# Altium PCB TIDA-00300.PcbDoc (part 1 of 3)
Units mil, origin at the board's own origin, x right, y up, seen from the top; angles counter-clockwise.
Board outline 2685 x 3089 mil, 4 copper layers (Top Layer, L2_GND-PLANE, L3_PWR-PLANE, Bottom Layer), stack 63.6 mil thick; 196 components, 87 nets, 476 pads, 171 vias.
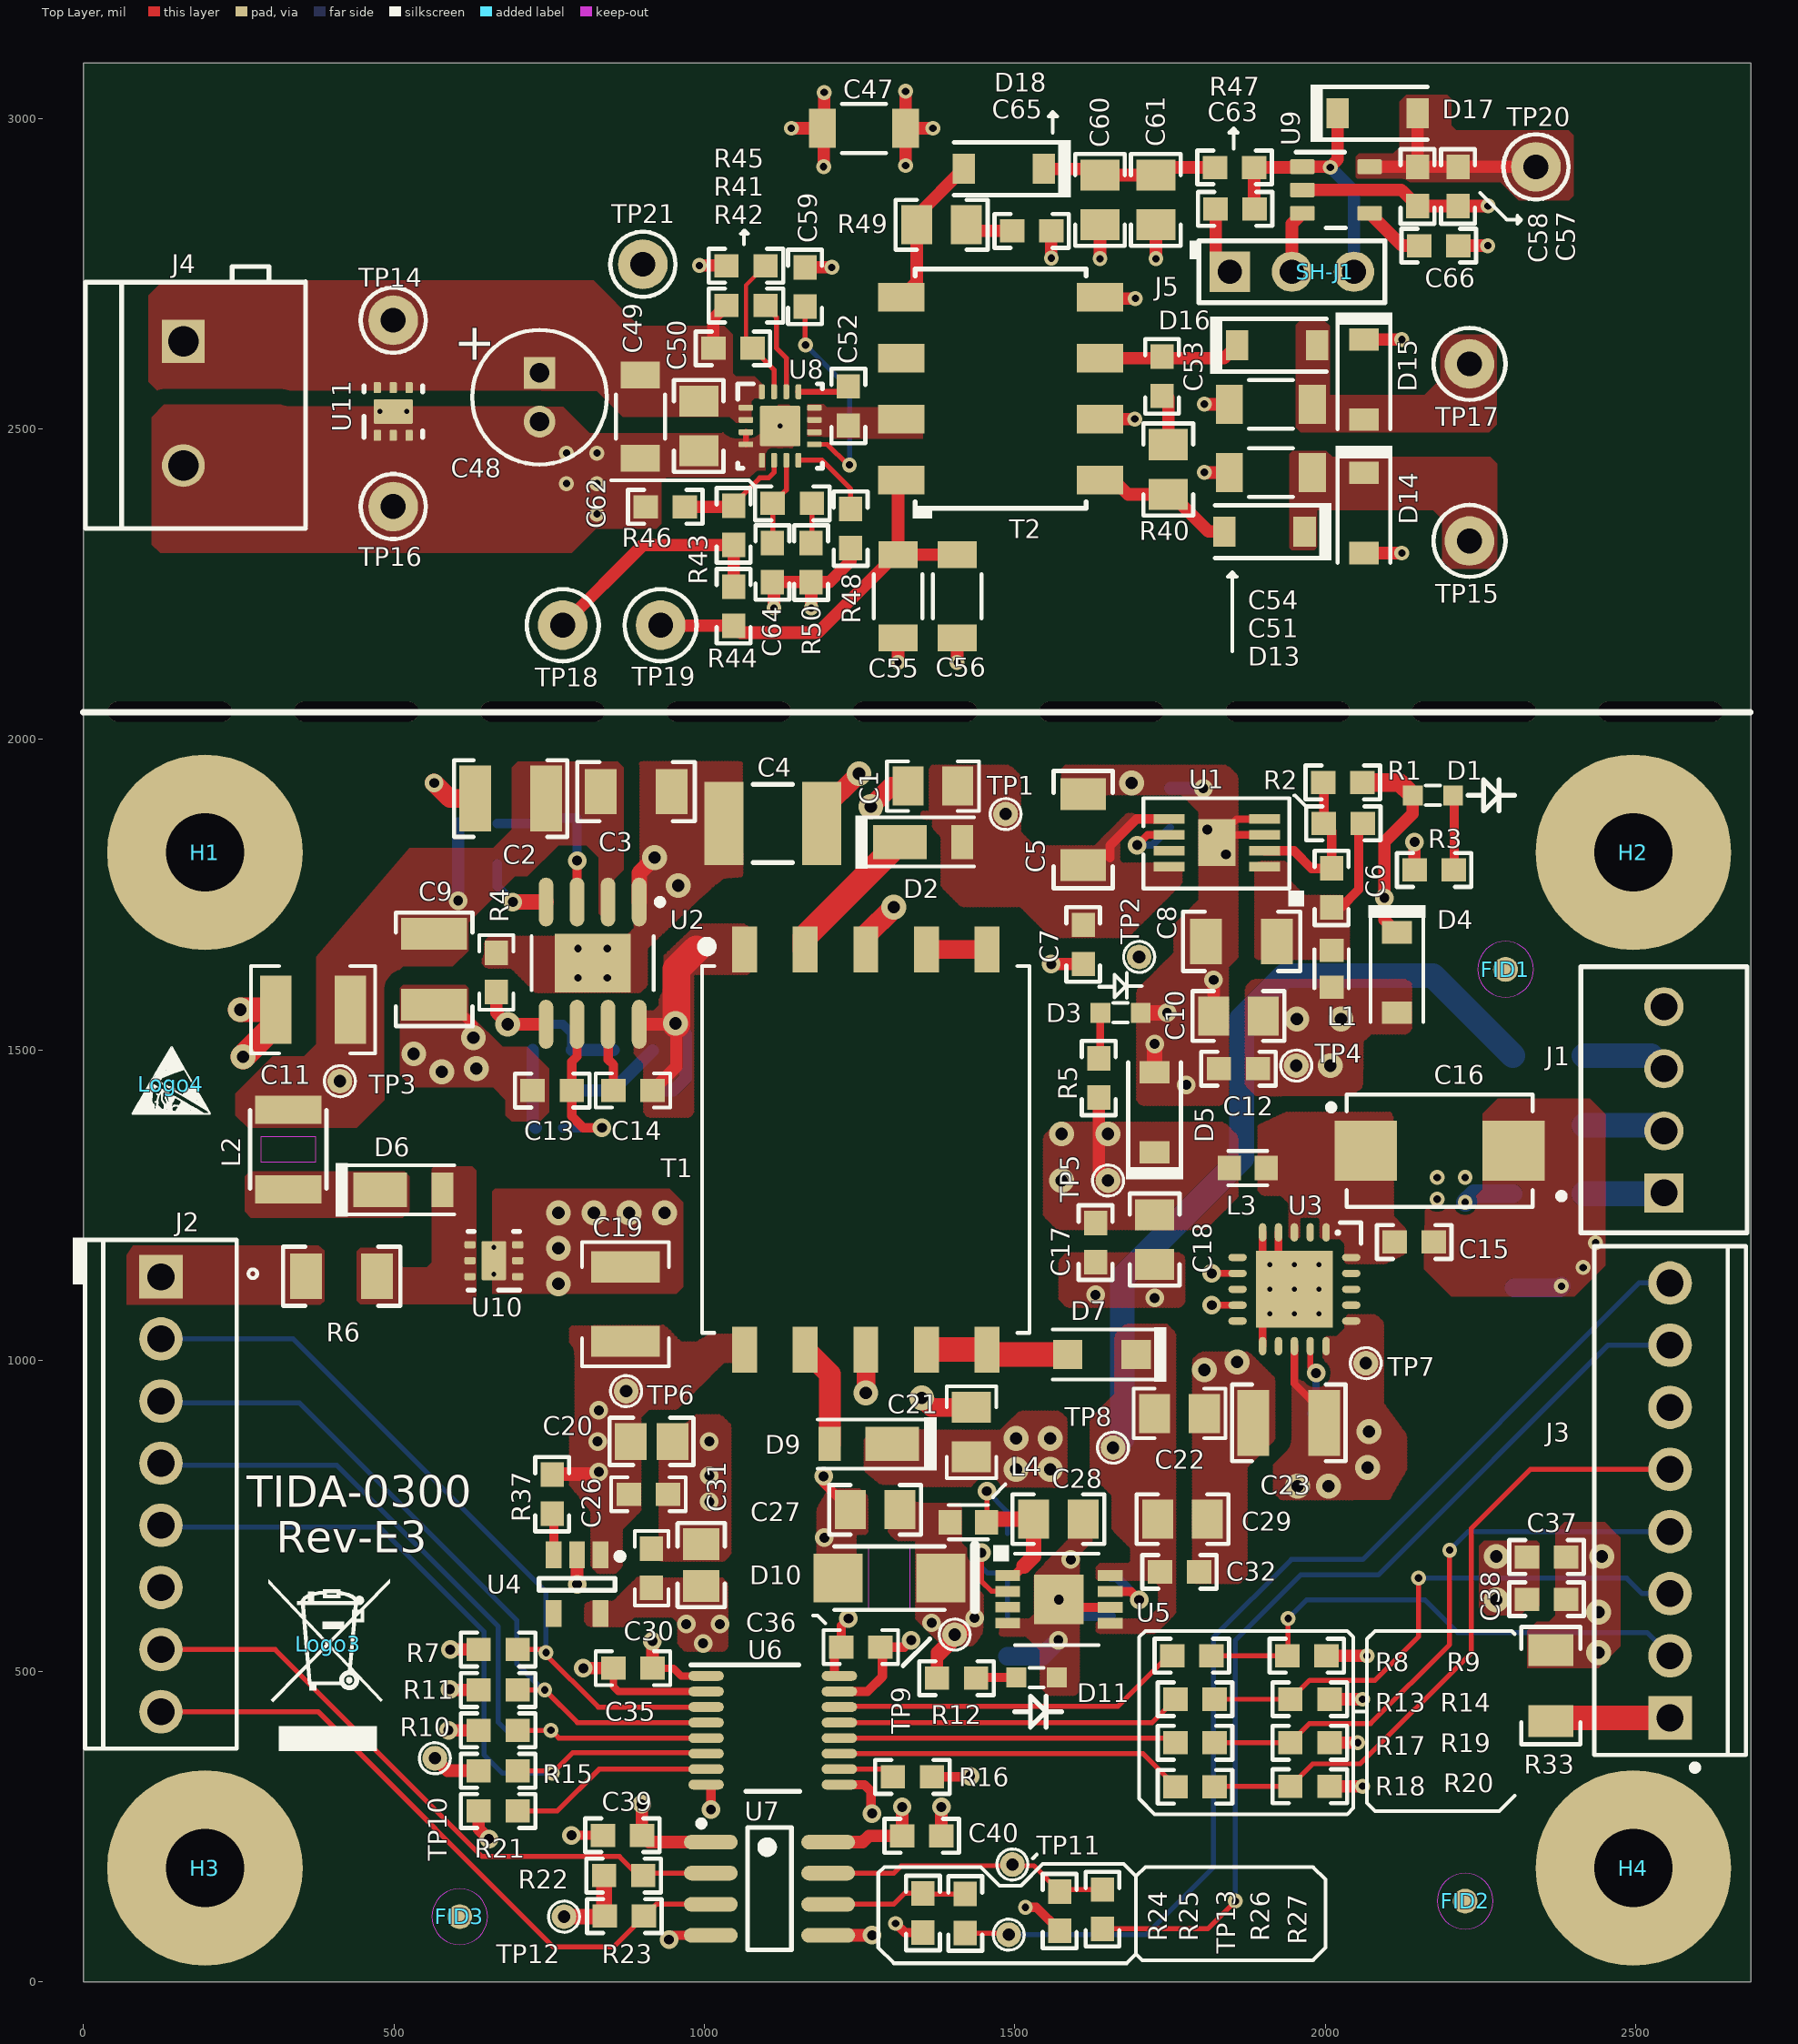
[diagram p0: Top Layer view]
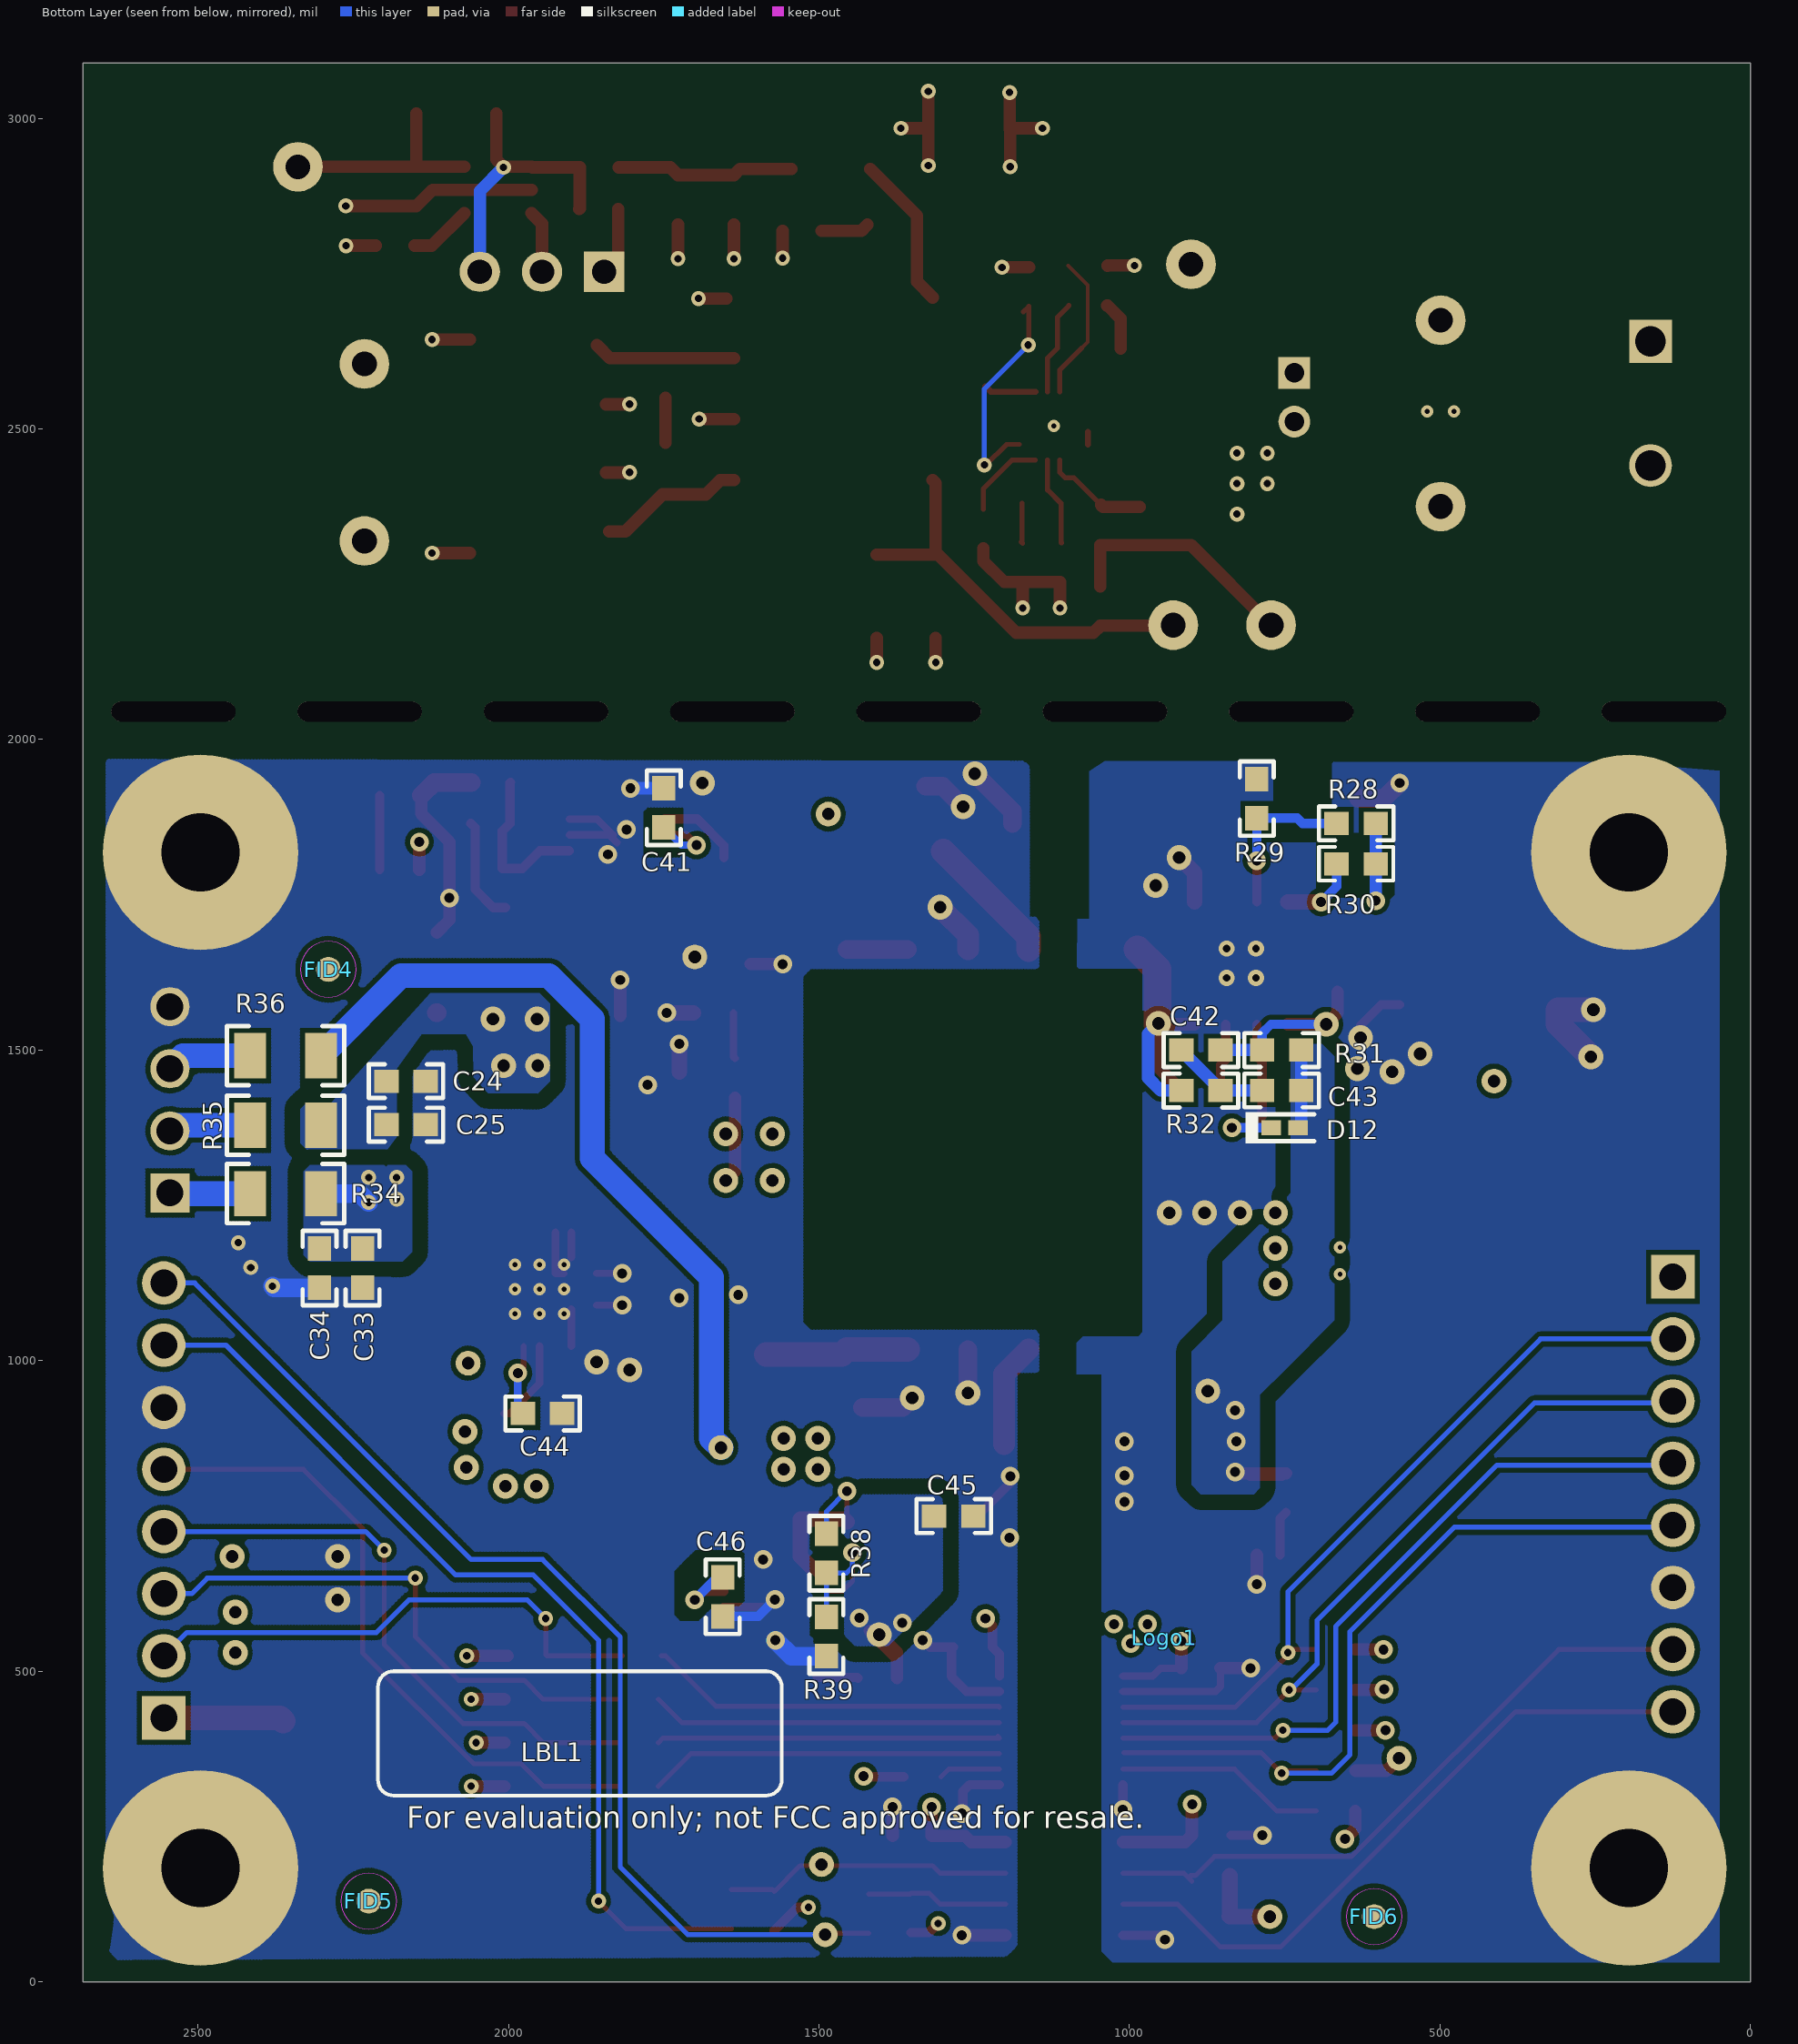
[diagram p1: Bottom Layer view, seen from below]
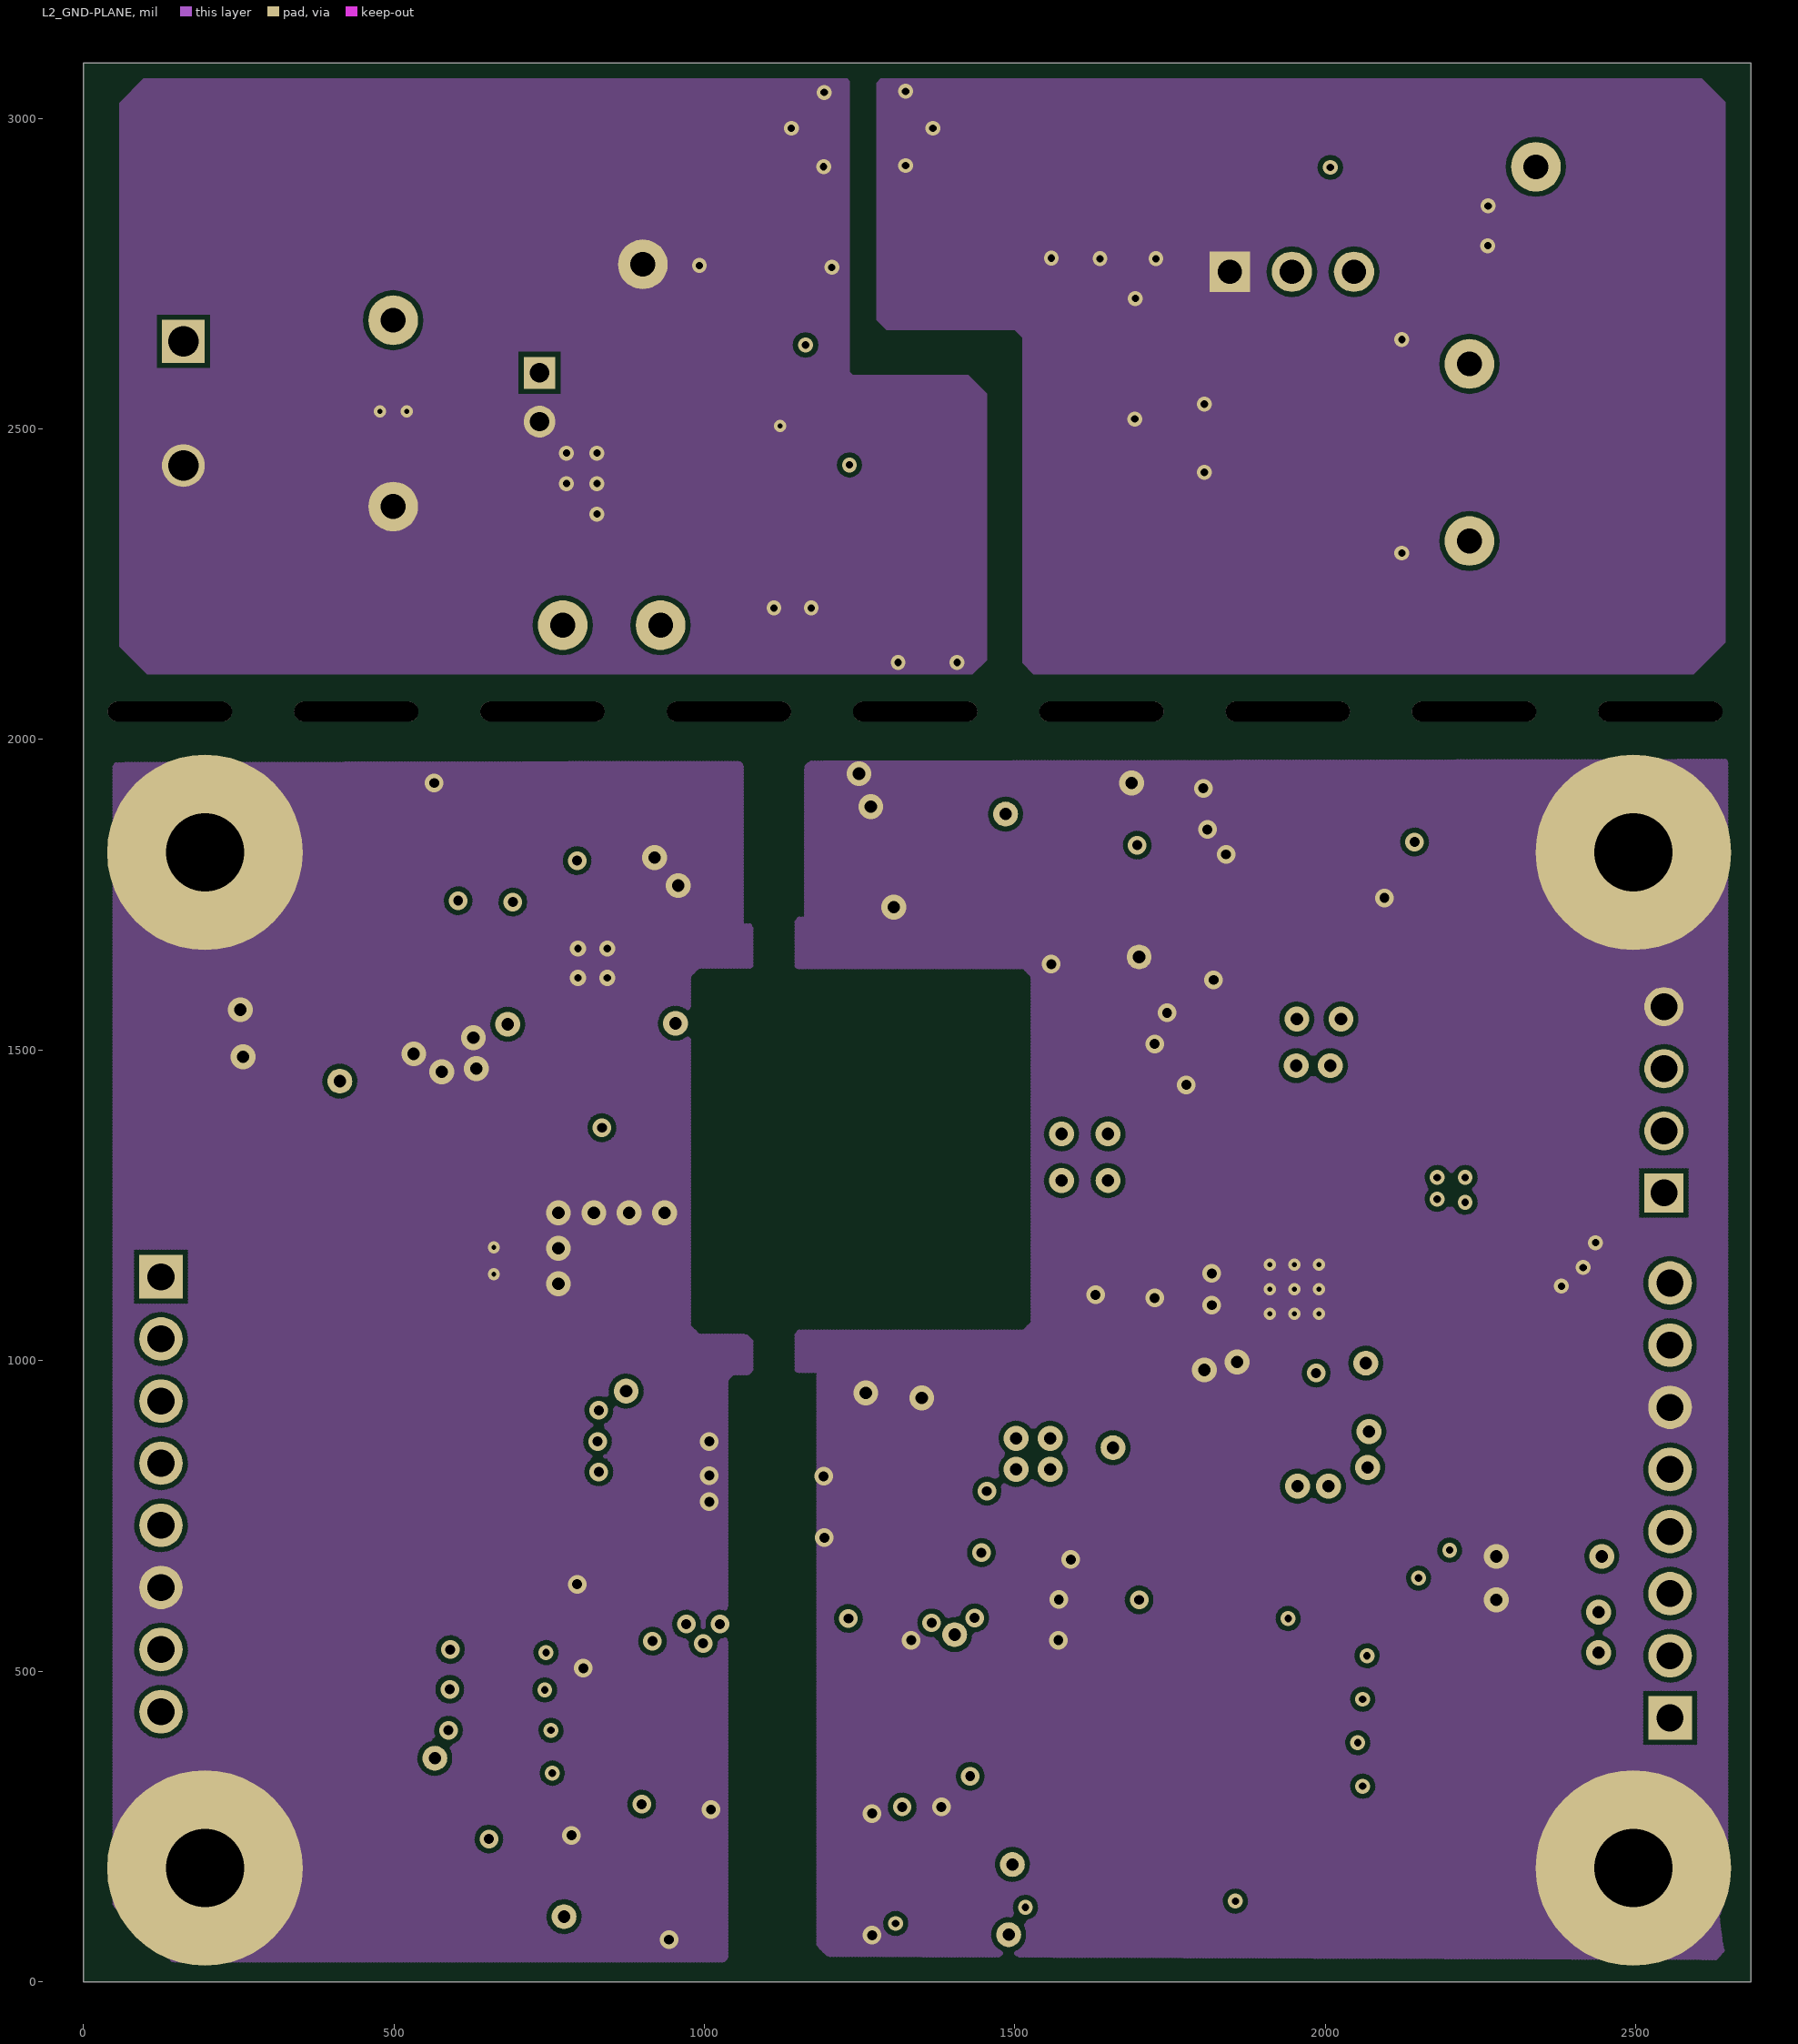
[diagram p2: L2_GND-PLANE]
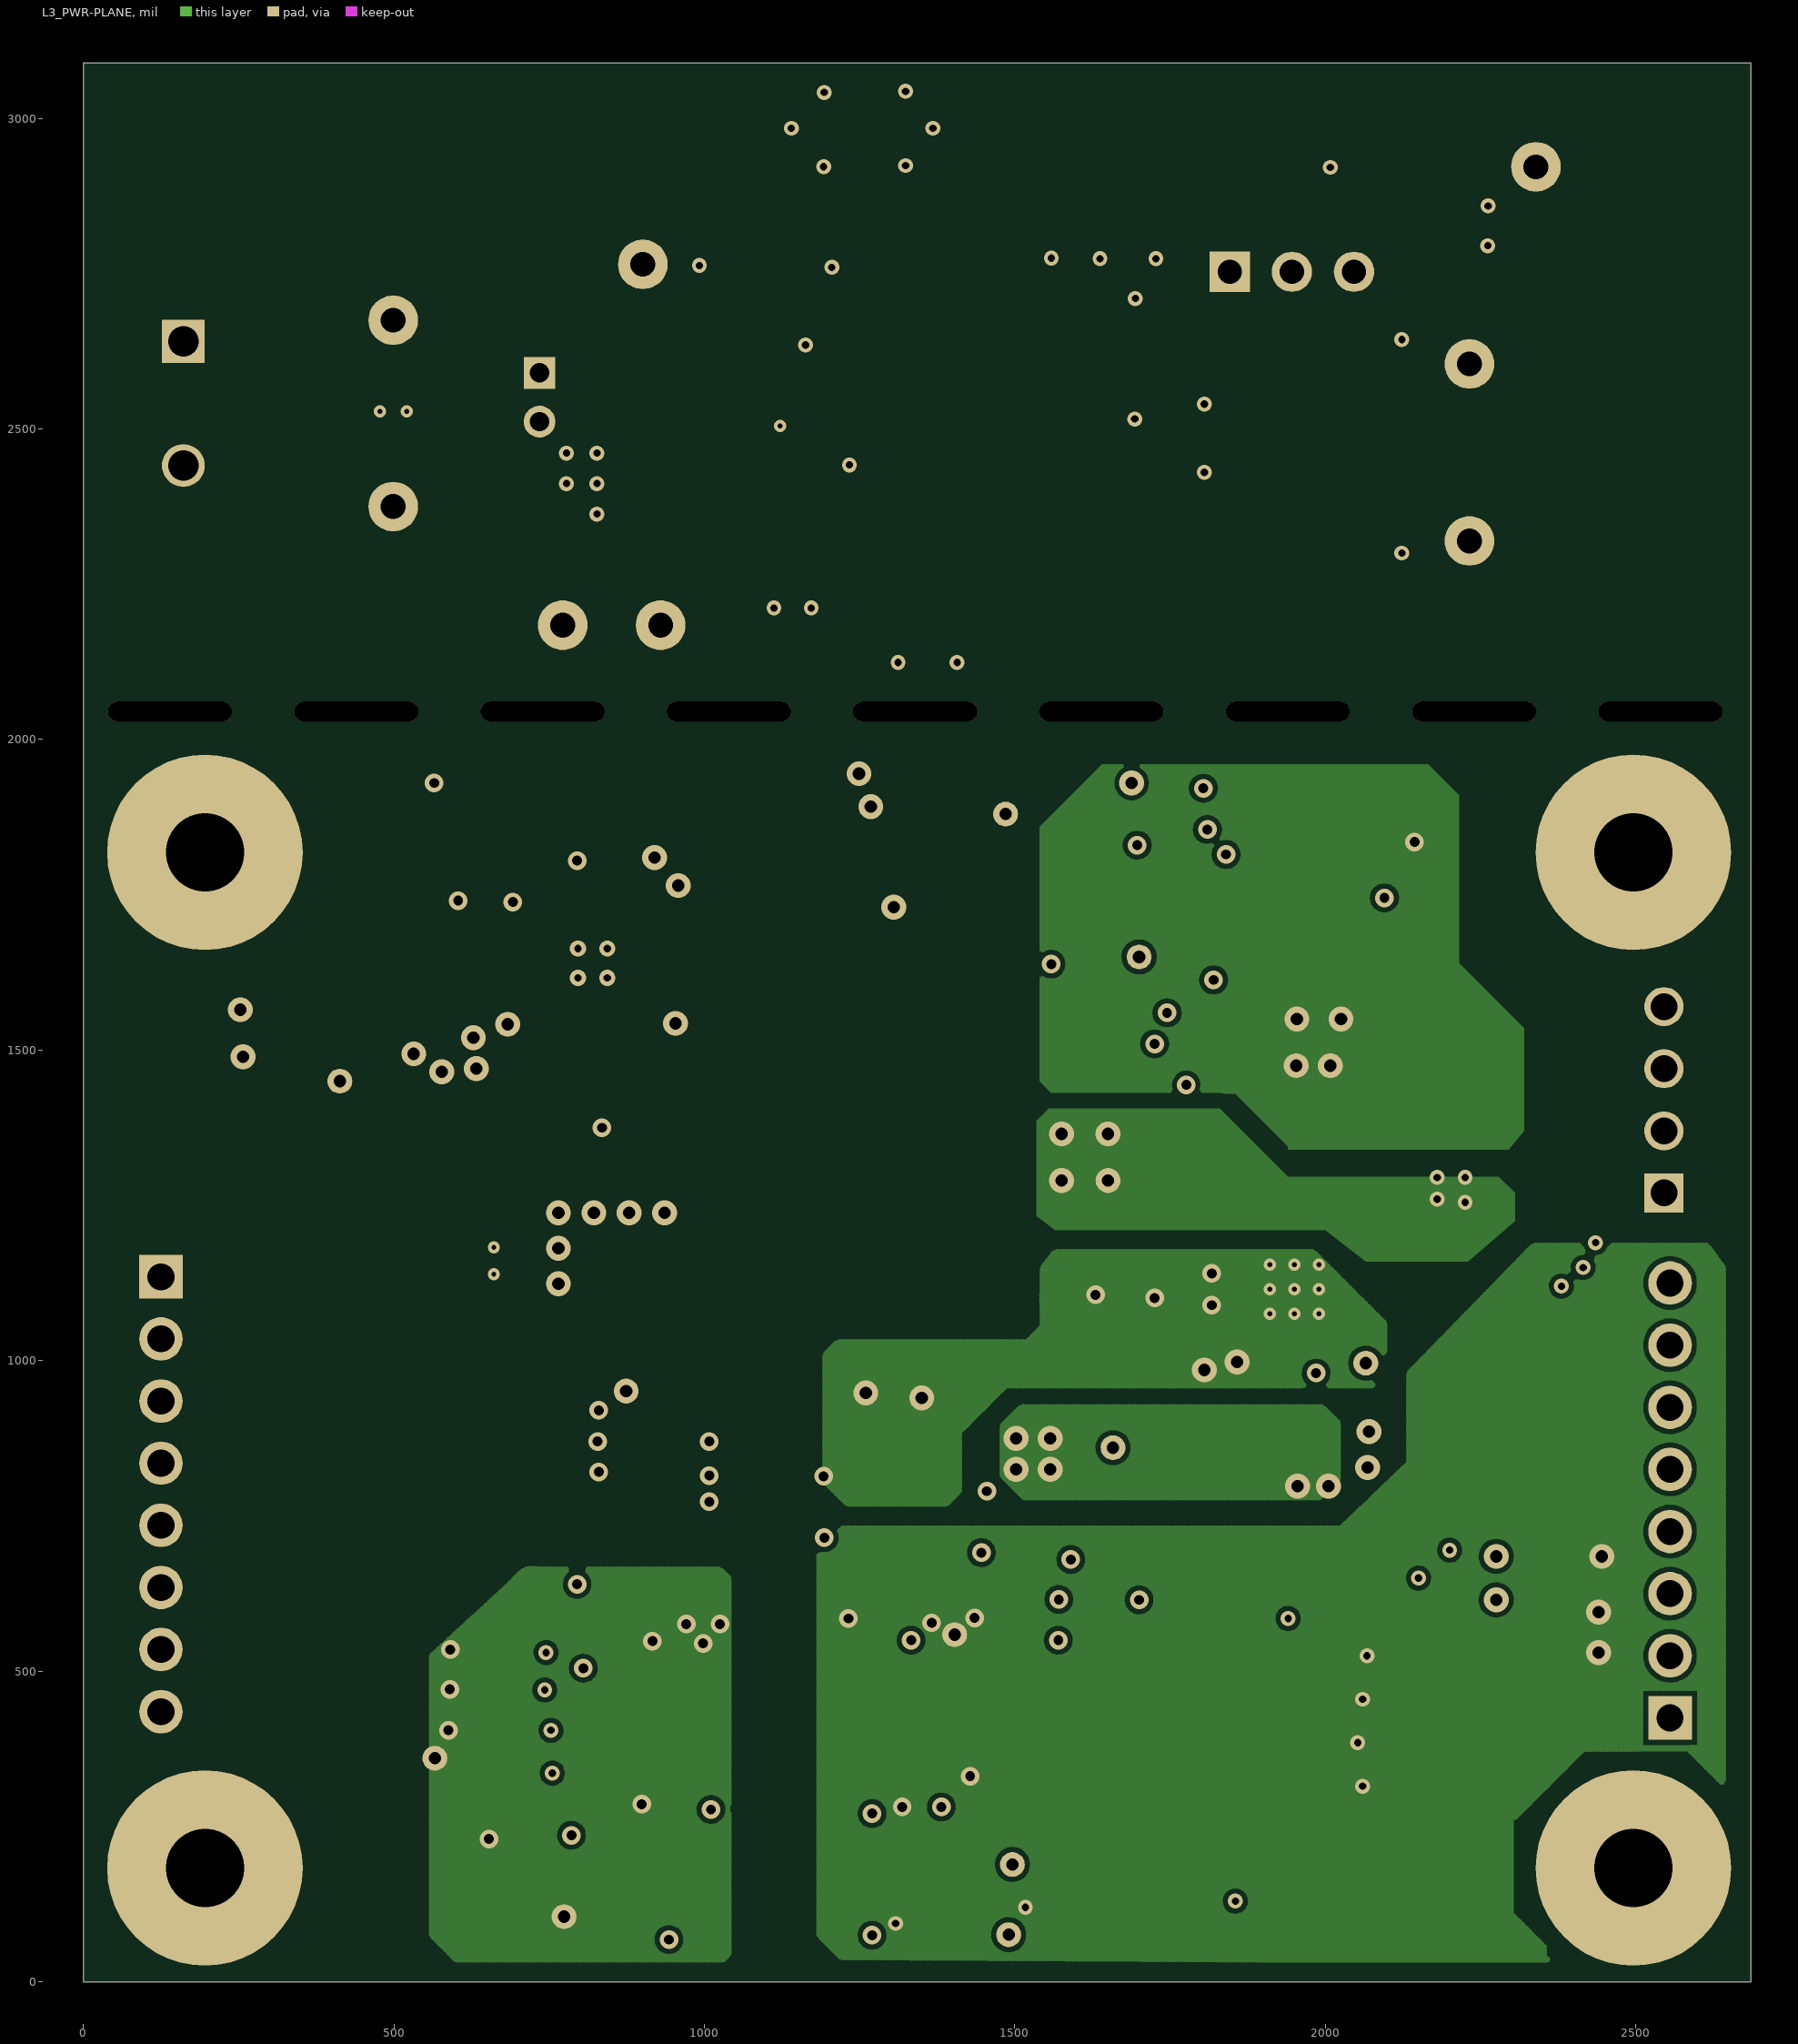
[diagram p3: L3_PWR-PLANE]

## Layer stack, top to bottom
Top Solder: solder mask 0.4, Solder Resist, Dk 3.5
Top Layer: signal copper 1.4
Dielectric1: core 23, FR-4 High Tg, Dk 4.8
L2_GND-PLANE: signal copper 1.4
Dielectric2: prepreg 12, FR-4 High Tg, Dk 4.8
L3_PWR-PLANE: signal copper 1.4
Dielectric3: core 23, FR-4 High Tg, Dk 4.8
Bottom Layer: signal copper 1.4
Bottom Solder: solder mask 0.4, Solder Resist, Dk 3.5

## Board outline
0,0 0,3089 2685,3089 2685,0

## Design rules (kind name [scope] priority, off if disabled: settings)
AcuteAngle [All] p1: minimum=4.50000000000000E+0001 checktracksonly=FALSE
AssemblyTestPointUsage [All] p1: valid=2
Clearance "U7 AND U9 Pad Class" [(InPadClass('Less Than 7.7')) vs (InPadClass('Less Than 7.7'))] p1: gap=7.8 ignorepadtopadclearanceinfootprint=FALSE except(0: Arc-Hole Track-Hole SMDPad-Hole THPad-Hole Via-Hole Fill-Hole Poly-Hole Region-Hole Text-Hole)
Clearance "Clearance_Poly to Poly" [InPolygon vs InPolygon] p2: gap=25 ignorepadtopadclearanceinfootprint=FALSE except(0: Arc-Hole Track-Hole SMDPad-Hole THPad-Hole Via-Hole Fill-Hole Poly-Hole Region-Hole Text-Hole)
Clearance "Clearance_VIA TO VIA" [IsVia vs IsVia] p3: gap=10 ignorepadtopadclearanceinfootprint=FALSE except(0: Arc-Hole Track-Hole SMDPad-Hole THPad-Hole Via-Hole Fill-Hole Poly-Hole Region-Hole Text-Hole)
Clearance "Clearance_Via to SMD" [IsVia vs IsSMTPin] p4: gap=6 ignorepadtopadclearanceinfootprint=FALSE except(0: Arc-Hole Track-Hole SMDPad-Hole THPad-Hole Via-Hole Fill-Hole Poly-Hole Region-Hole Text-Hole)
Clearance Clearance_BoardEdge_MountingHoles [OnCopper and InComponentClass('Mounting Holes') vs IsKeepOut] p5: gap=40 ignorepadtopadclearanceinfootprint=FALSE except(0: Arc-Hole Track-Hole SMDPad-Hole THPad-Hole Via-Hole Fill-Hole Poly-Hole Region-Hole Text-Hole)
Clearance Clearance_Poly [InPolygon vs IsTrack and IsVia and IsSMTPin and IsThruPin] p6: gap=12 ignorepadtopadclearanceinfootprint=FALSE except(0: Arc-Hole Track-Hole SMDPad-Hole THPad-Hole Via-Hole Fill-Hole Poly-Hole Region-Hole Text-Hole)
Clearance [All] p7: gap=8 ignorepadtopadclearanceinfootprint=FALSE except(0: Arc-Arc Arc-Track Arc-SMDPad Arc-THPad Arc-Hole Track-Hole SMDPad-Hole THPad-Hole Via-Hole Fill-Hole Poly-Hole Region-Hole Text-Hole)
ComponentClearance ComponentClearance_Logo [InComponentClass('Logo')] p1: gap=50 collisioncheckmode=3 verticalgap=10 showdistances=FALSE
ComponentClearance ComponentClearance_ScrewToNut [(HasFootprint('NY PMS 440 0025 PH')) vs (HasFootprint('Keystone_1902C'))] p2: gap=5 collisioncheckmode=3 verticalgap=10 showdistances=FALSE
ComponentClearance ComponentClearance_MountingHoles [InComponentClass('Mounting Holes')] p3: gap=250 collisioncheckmode=3 verticalgap=100000 showdistances=FALSE
ComponentClearance ComponentClearance_SmallPassives [HasFootprint('0201*') or HasFootprint('0402*') or HasFootprint('0508') or HasFootprint('0603*') or HasFootprint('0612') or HasFootprint('0805*') or HasFootprint('0815*') or HasFootprint('0830*') or HasFootprint('1206*') or HasFootprint('1210*') or HasFootprint('1808*') or HasFootprint('1812*') or HasFootprint('1825*') or HasFootprint('2010*') or HasFootprint('2220*') or HasFootprint('2225*') or HasFootprint('2512*') or HasFootprint('2728*') or HasFootprint('3518*') vs HasFootprint('0201*') or HasFootprint('0402*') or HasFootprint('0508') or HasFootprint('0603*') or HasFootprint('0612') or HasFootprint('0805*') or HasFootprint('0815*') or HasFootprint('0830*') or HasFootprint('1206*') or HasFootprint('1210*') or HasFootprint('1808*') or HasFootprint('1812*') or HasFootprint('1825*') or HasFootprint('2010*') or HasFootprint('2220*') or HasFootprint('2225*') or HasFootprint('2512*') or HasFootprint('2728*') or HasFootprint('3518*')] p4: gap=20 collisioncheckmode=3 verticalgap=10 showdistances=FALSE
ComponentClearance ComponentClearance_THtoSMT [IsThruComponent vs IsSMTComponent] p5: gap=100 collisioncheckmode=3 verticalgap=30 showdistances=FALSE
ComponentClearance ComponentClearance_THtoTH [IsThruComponent vs IsThruComponent] p6: gap=118.11 collisioncheckmode=3 verticalgap=30 showdistances=FALSE
ComponentClearance [All] p7: gap=40 collisioncheckmode=3 verticalgap=10 showdistances=FALSE
DiffPairsRouting [All] p1: maxlimit=100 minlimit=10 mostfreqgap=10 toplayer_minwidth=15 toplayer_maxwidth=15 toplayer_prefwidth=15 midlayer1_minwidth=15 midlayer1_maxwidth=15 midlayer1_prefwidth=15 midlayer2_minwidth=15 midlayer2_maxwidth=15 midlayer2_prefwidth=15 bottomlayer_minwidth=15 bottomlayer_maxwidth=15 bottomlayer_prefwidth=15 maxuncoupledlength=1000
FabricationTestPointUsage TestPointUsage [All] p1: valid=2 allowmultiple=FALSE
FabricationTestpoint Testpoint [All] p1: side=3 testpointundercomponent=TRUE minsize=40 maxsize=100 preferedsize=60 minholesize=0 maxholesize=40 preferedholesize=32 testpointgrid=1 allowsidetop=TRUE allowsidebottom=TRUE usegrid=TRUE gridtolerance=0.01
FanoutControl Fanout_LCC [IsLCC] p1: bgadir=Out bgaviamode=Centered fanoutstyle=Auto fanoutdirection=Alternating viagrid=1 // Fanout_LCC (Default Rule)
FanoutControl Fanout_BGA [IsBGA] p2: bgadir=Out bgaviamode=Centered fanoutstyle=Auto fanoutdirection=Alternating viagrid=1 // Fanout_BGA (Default Rule)
FanoutControl Fanout_Default [All] p4: bgadir=Out bgaviamode=Centered fanoutstyle=Auto fanoutdirection=Alternating viagrid=1 // Fanout_Default (Default Rule)
FanoutControl Fanout_Small [(CompPinCount < 5)] p5: bgadir=Out bgaviamode=Centered fanoutstyle=Auto fanoutdirection=OutThenIn viagrid=1 // Fanout_Small (Default Rule)
HoleSize [All] p1: absolutevalues=TRUE maxlimit=251 minlimit=7.8 maxpercent=80.000 minpercent=20.000
MinimumAnnularRing MinimumAnnularRing_ThermalPadVias [IsVia and InAnyComponent] p1: minimumring=5.91
MinimumAnnularRing [All] p2: minimumring=6
MinimumSolderMaskSliver MinimumSolderMaskSliver_Logo [InComponentClass('Logo') vs InComponentClass('Logo')] p1: minsoldermaskwidth=0.7
MinimumSolderMaskSliver [All] p2: minsoldermaskwidth=3.94
PlaneClearance [All] p1: clearance=16
PlaneConnect [All] p1: planeconnectstyle=Direct reliefexpansion=10 reliefentries=4 reliefconductorwidth=10 reliefairgap=10
PolygonConnect [All] p1: connectstyle=Direct reliefconductorwidth=10 reliefentries=4 polygonreliefangle="90 Angle" airgapwidth=10
RoutingVias RoutingVias_PWR [InNetClass('PWR')] p1: holewidth=20 width=40 viastyle="Through Hole" minholewidth=20 minwidth=40 maxholewidth=20 maxwidth=40
RoutingVias [InNetClass('All Nets')] p2: holewidth=16 width=30 viastyle="Through Hole" minholewidth=7.87 minwidth=19.68 maxholewidth=20 maxwidth=40
RoutingVias ThermalPadVias [IsVia and InAnyComponent] p3: holewidth=7.87 width=19.68 viastyle="Through Hole" minholewidth=7.87 minwidth=19.68 maxholewidth=12.99 maxwidth=23.62
SMDToCorner [All] p1: distance=30000
SilkToSilkClearance [All] p1: silktosilkclearance=5
SilkToSolderMaskClearance SilkscreenOverComponentPads [IsPad] p1 off: minsilkscreentomaskgap=5 clearancetoexposedcopper=TRUE
SolderMaskExpansion [All] p1: expansion=2.5
Width Width_PWR [InNetClass('PWR')] p1: maxlimit=100 minlimit=8 preferedwidth=10
Width [All] p2: maxlimit=100 minlimit=6 preferedwidth=8 checkconnectedcopper=TRUE
15 further rules are at their usual default settings.

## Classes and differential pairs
component class "TIDA-00300_Power Stage_Pg5": C47 C48 C49 C50 C51 C52 C53 C54 C55 C56 C57 C58 C59 C60 C61 C62 C63 C64 C65 C66 D13 D14 D15 D16 D17 D18 J4 J5 R40 R41 R42 R43 R44 R45 R46 R47 R48 R49 R50 SH-J1 T2 TP14 TP15 TP16 TP17 TP18 TP19 TP20 TP21 U8 U9 U11
component class Header: J5
component class TIDA-00300_EVM_Hardware_Pg6: !PCB FID1 FID2 FID3 FID4 FID5 FID6 H1 H2 H3 H4 LBL1 Logo1 Logo2 Logo3 Logo4 ZZ1 ZZ2 ZZ3 ZZ4
component class "Mounting Holes": H1 H2 H3 H4
component class "TIDA-00300_Isolated Power Supply +15V,-15V & +5V_Pg4 ": C5 C6 C7 C8 C10 C12 C15 C16 C17 C18 C23 C27 C28 C29 C32 C41 C44 C45 C46 D1 D3 D4 D5 D10 D11 L1 L3 L4 R1 R2 R3 R5 R12 R38 R39 TP4 TP5 TP9 U1 U3 U5
component class Label: LBL1
component class AssemblyNote: ZZ1 ZZ2 ZZ3 ZZ4
component class "TIDA-00300_Isolated SPI, I2C & Fly buck Power Supply_Pg3 ": C1 C2 C3 C4 C9 C11 C13 C14 C19 C20 C21 C22 C24 C25 C26 C30 C31 C33 C34 C35 C36 C37 C38 C39 C40 C42 C43 D2 D6 D7 D9 D12 J1 J2 J3 L2 R4 R6 R7 R8 R9 R10 R11 R13 R14 R15 R16 R17 R18 R19 R20 R21 R22 R23 R24 R25 R26 R27 R28 R29 R30 R31 R32 R33 R34 R35 R36 R37 T1 TP1 TP2 TP3 TP6 TP7 TP8 TP10 TP11 TP12 TP13 U2 U4 U6 U7 U10

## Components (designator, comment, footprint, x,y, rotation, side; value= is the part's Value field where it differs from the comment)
C1 "GRM21BR71E225KA73L" 0805_HV 1368,1925 r0 top value=2.2uF
C2 "GRM32ER72A225KA35L" 1210#1 688,1905 r0 top value=2.2uF
C3 "ESD61C474K4T2A-28" 1206 890,1916 r180 top value=0.47uF
C4 "1812GC102KAT1A" 1812 1110,1865 r180 top value=1000pF
C5 "GRM31CR71H475KA12L" 1206 1610,1855 r90 top value=4.7uF
C6 "06031C103JAT2A" 0603 2010,1761 r90 top value=0.01uF
C7 "06035C104KAT2A" 0603 1610,1670 r90 top value=0.1uF
C8 "GRM31CR71E106KA12L" 1206 1865,1675 r180 top value=10uF
C9 "GRM32ER71H106KA12L" 1210#1 565,1630 r270 top value=10uF
C10 "C2012X5R1H475K125AB" 0805_HV 1860,1555 r0 top value=4.7uF
C11 "GRM32ER72A225KA35L" 1210#2 370,1565 r180 top value=2.2uF
C12 "06035C104KAT2A" 0603 1860,1470 r0 top value=0.1uF
C13 "C1608X5R1H105K080AB" 0603 755,1435 r180 top value=1uF
C14 "06031C103JAT2A" 0603 885,1435 r0 top value=0.01uF
C15 "06035C104KAT2A" 0603 2143,1191 r180 top value=0.1uF
C16 "T495X476K035ATE300" 7343-43 2184,1338 r0 top value=47uF
C17 "06035C104KAT2A" 0603 1630,1190 r90 top value=0.1uF
C18 "C2012X5R1H475K125AB" 0805_HV 1725,1195 r270 top value=4.7uF
C19 "GMK325AB7106MM-T" 1210#2 873,1091 r270 top value=10uF
C20 "08055C105KAT2A" 0805 915,870 r0 top value=1uF
C21 "GRM21BR71E225KA73L" 0805_HV 1430,885 r90 top value=2.2uF
C22 "GRM21BR71E225KA73L" 0805_HV 1765,915 r0 top value=2.2uF
C23 "GRM32ER71H106KA12L" 1210#1 1941,900 r180 top value=10uF
C24 "C1608X5R1H105K080AB" 0603 2165,1450 r180 bottom value=1uF
C25 "GRM188R72A104KA35D" 0603 2165,1380 r0 bottom value=0.1uF
C26 "C0603C104K5RACTU" 0603 910,785 r0 top value=0.1uF
C27 "C2012X5R1H475K125AB" 0805_HV 1275,760 r180 top value=4.7uF
C28 "GRM21BR61C226ME44" 0805_HV 1570,745 r0 top value=22uF
C29 "GRM21BR61C226ME44" 0805_HV 1770,745 r0 top value=22uF
C30 "C0603C104K5RACTU" 0603 915,666 r90 top value=0.1uF
C31 "0805YD106MAT2A" 0805 995,671 r90 top value=10uF
C32 "06035C104KAT2A" 0603 1765,660 r180 top value=0.1uF
C33 "C1608X5R1H105K080AB" 0603 2235,1149 r90 bottom value=1uF
C34 "GRM188R72A104KA35D" 0603 2304,1149 r90 bottom value=0.1uF
C35 "C0603C104K5RACTU" 0603 885,505 r0 top value=0.1uF
C36 "C0603C104K5RACTU" 0603 1252,539 r0 top value=0.1uF
C37 "C1608X5R1H105K080AB" 0603 2356,684 r180 top value=1uF
C38 "GRM188R72A104KA35D" 0603 2356,616 r0 top value=0.1uF
C39 "C0603C104K5RACTU" 0603 868,236 r0 top value=0.1uF
C40 "C0603C104K5RACTU" 0603 1350,235 r0 top value=0.1uF
C41 "06031C103JAT2A" 0603 1750,1890 r90 bottom value=0.01uF
C42 "GRM188R72A104KA35D" 0603 885,1500 r180 bottom value=0.1uF
C43 "06031C332JAT2A" 0603 755,1435 r180 bottom value=3300pF
C44 "C1608X7R1E105K080AB" 0603 1945,915 r180 bottom value=1uF
C45 "06035C104KAT2A" 0603 1283,750 r0 bottom value=0.1uF
C46 "06031C102JAT2A" 0603 1655,620 r270 bottom value=1000pF
C47 "202R18W102KV4E" 1206_190 1257,2983.67 r180 top value=1000pF
C48 "ECA-1VM470" CAPPRD200W50D500H1100 734.61,2551 r270 top value=47uF
C49 "GRM31CR71A226KE15L" 1206_180 897,2519.67 r270 top value=22uF
C50 "C2012X7R1A106K125AC" 0805_HV 990.9,2504.67 r90 top value=10uF
C51 "GRM31CR71H225KA88L" 1206_180 1912,2429.67 r180 top value=2.2uF
C52 "GRM188R71H104KA93D" 0603 1232,2537 r90 top value=0.1uF
C53 "GRM1885C1H150JA01D" 0603 1737,2584.67 r90 top value=15pF
C54 "GRM31CR71H225KA88L" 1206_180 1912,2539.67 r0 top value=2.2uF
C55 "GRM31CR71A226KE15L" 1206_180 1312,2230.67 r270 top value=22uF
C56 "GRM31CR71A226KE15L" 1206_180 1407,2230.67 r270 top value=22uF
C57 "GRM188R71A225KE15D" 0603 2213.33,2890.39 r270 top value=2.2uF
C58 "GRM188R71A225KE15D" 0603 2148.33,2890.39 r270 top value=2.2uF
C59 "GRM188R71H104KA93D" 0603 1162,2728.67 r90 top value=0.1uF
C60 "C2012X7R1A106K125AC" 0805_HV 1637,2868.67 r270 top value=10uF
C61 "C2012X7R1A106K125AC" 0805_HV 1727,2868.67 r90 top value=10uF
C62 "GRM188R71H333KA61D" 0603 1141.61,2380 r0 top value=0.033uF
C63 "GRM188R71A225KE15D" 0603 1854.69,2854.14 r180 top value=2.2uF
C64 "GRM1885C1H820JA01D" 0603 1109.61,2285 r90 top value=82pF
C65 "GRM1885C1H150JA01D" 0603 1527,2818.67 r0 top value=15pF
C66 "06031C103KAT2A" 0603 2182.5,2795 r0 top value=0.01uF
D1 "LED_LG L29K-G2J1-24-Z" LED0603AA 2173,1910 r180 top value=Green
D2 "DFLS1200-7" powerDI123 1365,1835 r0 top value=200V
D3 "LED_LG L29K-G2J1-24-Z" LED0603AA 1670,1560 r180 top value=Green
D4 "DZ2W18000L" SOD-123 2115,1625 r270 top value=18V
D5 "DZ2W18000L" SOD-123 1725,1400 r90 top value=18V
D6 "DFLS1200-7" powerDI123 528,1275 r0 top value=200V
D7 "PMEG6010CEH,115" SOD-123F 1640,1010 r180 top value=60V
D9 "DFLS1200-7" powerDI123 1252,866 r180 top value=200V
D10 "PTZTE255.6B" DIO_SOD-106 1298,650 r180 top value=5.9V
D11 "LED_LG L29K-G2J1-24-Z" LED0603AA 1535,490 r180 top value=Green
D12 "SDM10U45-7-F" SOD-523 750,1375 r180 bottom value=45V
D13 "BAT41ZFILM" SOD-123 1902,2334.67 r180 top value=100V
D14 "MMSZ4703T1G" SOD-123 2062,2364.67 r270 top value=16V
D15 "MMSZ4703T1G" SOD-123 2062,2579.67 r270 top value=16V
D16 "BAT41ZFILM" SOD-123 1922,2634.67 r0 top value=100V
D17 "B0530W-7-F" SOD-123 2084,3008 r0 top value=30V
D18 "B0530W-7-F" SOD-123 1482,2918.67 r180 top value=30V
FID1 "Fiducial40_80" FID_TOP_40_80BA 2290,1630 r90 top
FID2 "Fiducial40_80" FID_TOP_40_80BA 2225,130 r0 top
FID3 "Fiducial40_80" FID_TOP_40_80BA 606,105 r90 top
FID4 "Fiducial40_80" FID_TOP_40_80BA 2290,1630 r180 bottom
FID5 "Fiducial40_80" FID_TOP_40_80BA 2225,130 r90 bottom
FID6 "Fiducial40_80" FID_TOP_40_80BA 606,105 r90 bottom
H1 "NY PMS 440 0025 PH" "NY PMS 440 0025 PH" 195,1825 r0 top
H2 "NY PMS 440 0025 PH" "NY PMS 440 0025 PH" 2495,1825 r0 top
H3 "NY PMS 440 0025 PH" "NY PMS 440 0025 PH" 195,190 r0 top
H4 "NY PMS 440 0025 PH" "NY PMS 440 0025 PH" 2495,190 r0 top
J1 "282834-4" TEC_282834-4 2545,1420 r90 top
J2 "1725711" CONN_1725711 125,785 r270 top
J3 "1725711" CONN_1725711 2555,775 r90 top
J4 "ED120/2DS" CONN_ED120-2DS 161,2541 r180 top
J5 "5-146278-3" TE_5-146278-3 1946,2753 r0 top
L1 "1000 OHM" FB0603 2010,1631 r270 top
L2 "3.3µH" IND_B82422H 330,1340 r90 top
L3 "1000 OHM" FB0603 1875,1310 r180 top
L4 "1000 OHM" FB0603 1425,740 r180 top
LBL1 "Size: 0.65\" x 0.20 \"" Label_650x200 1885,400 r180 bottom
Logo1 "Pb-Free Symbol" Pb-Free_Overlay_Small 944,554 r180 bottom
Logo2 "FCC disclaimer" FCC_disclaimer 3461,588 r90 top
Logo3 "WEEE logo" WEEE_Minimum 394,544 r0 top
Logo4 "ESD Susceptible" ESD_Overlay_small 140.78,1445.01 r0 top
R1 "RNCF0603FKE9K42" 0603 2028,1931 r0 top value=9.42k
R2 "RG1608P-114-B-T5" 0603 2029,1865 r0 top value=110k
R3 "CRCW06034K70JNEA" 0603 2175,1790 r0 top value=4.7k
R4 "RC0603FR-0727KL" 0603 665,1625 r270 top value=27.0k
R5 "CRCW06034K70JNEA" 0603 1635,1455 r90 top value=4.7k
R6 "RC1206JR-070RL" 1206 416,1136 r180 top value=0
R7 "CRCW060310K0FKEA" 0603 668,535 r180 top value=10.0k
R8 "RC0603JR-070RL" 0603 1785,525 r0 top value=0
R9 "CRCW060310K0FKEA" 0603 1970,525 r0 top value=10.0k
R10 "CRCW060310K0FKEA" 0603 668,405 r180 top value=10.0k
R11 "CRCW060310K0FKEA" 0603 668,470 r180 top value=10.0k
R12 "RG1608P-122-B-T5" 0603 1406,489 r180 top value=1.20k
R13 "RC0603JR-070RL" 0603 1790,455 r0 top value=0
R14 "CRCW060310K0FKEA" 0603 1975,455 r0 top value=10.0k
R15 "CRCW060310K0FKEA" 0603 668,340 r180 top value=10.0k
R16 "RC0603JR-070RL" 0603 1335,330 r0 top value=0
R17 "RC0603JR-070RL" 0603 1790,385 r0 top value=0
R18 "RC0603JR-070RL" 0603 1790,314 r0 top value=0
R19 "CRCW060310K0FKEA" 0603 1975,385 r0 top value=10.0k
R20 "CRCW060310K0FKEA" 0603 1975,315 r0 top value=10.0k
R21 "RC0603JR-070RL" 0603 668,275 r0 top value=0
R22 "CRCW06031K50FKEA" 0603 870,171 r180 top value=1.50k
R23 "CRCW06031K50FKEA" 0603 871,106 r180 top value=1.50k
R24 "CRCW06031K50FKEA" 0603 1352,111 r270 top value=1.50k
R25 "RC0603JR-070RL" 0603 1420,110 r270 top value=0
R26 "CRCW06031K50FKEA" 0603 1572,114 r270 top value=1.50k
R27 "RC0603JR-070RL" 0603 1641,117 r270 top value=0
R28 "ERA-3AEB6042V" 0603 635,1865 r180 bottom value=60.4k
R29 "RC0603FR-074K87L" 0603 795,1905 r270 bottom value=4.87k
R30 "CRCW0603340KFKEA" 0603 635,1800 r180 bottom value=340k
R31 "ERA-3AEB1873V" 0603 755,1500 r180 bottom value=187k
R32 "ERA-3AEB5622V" 0603 885,1435 r0 bottom value=56.2k
R33 "RC1206JR-070RL" 1206 2363,477 r270 top value=0
R34 "RC1206JR-070RL" 1206 2359,1269 r0 bottom value=0
R35 "RC1206JR-070RL" 1206 2359,1379 r0 bottom value=0
R36 "RC1206JR-070RL" 1206 2359,1491 r0 bottom value=0
R37 "RC0603JR-070RL" 0603 755,785 r90 top value=0
R38 "TNPW060320K0BEEA" 0603 1488,690 r90 bottom value=20K
R39 "ERA-3AEB1132V" 0603 1488,556 r90 bottom value=11.3K
R40 "ERJ-6GEYJ102V" 0805_HV 1747,2434.67 r270 top value=1.0k
R41 "CRCW060310K0JNEA" 0603 1067,2698.67 r180 top value=10k
R42 "CRCW0603220KJNEA" 0603 1045.9,2629.67 r180 top value=220k
R43 "CRCW060316K2FKEA" 0603 1047,2344.67 r90 top value=16.2k
R44 "CRCW060349R9FKEA" 0603 1047,2214.67 r270 top value=49.9
R45 "CRCW060375K0JNEA" 0603 1067,2762.67 r0 top value=75k
R46 "CRCW060310K0FKEA" 0603 937,2374.67 r0 top value=10.0k
R47 "CRCW06030000Z0EA" 0603 1853.76,2921 r0 top value=0
R48 "CRCW0603240KJNEA" 0603 1235.54,2339.47 r90 top value=240k
R49 "ERJ-6GEYJ102V" 0805_HV 1382,2828.67 r180 top value=1.0k
R50 "CRCW060310K0JNEA" 0603 1172,2284.67 r90 top value=10k
SH-J1 "60900213421" Wurth_60900213421 1999,2753 r180 top
T1 "750342178" WURTH_750313995 1260,1340 r0 top value=50uH
T2 "750316449" Wurth_750316170 1477,2564.67 r90 top value=2.7uH
TP1 "TP1_PD40_D0.5_S50" TP1_PD40_D0.5_S50 1485,1880 r0 top value=STD
TP2 "TP1_PD40_D0.5_S50" TP1_PD40_D0.5_S50 1700,1650 r0 top value=STD
TP3 "TP1_PD40_D0.5_S50" TP1_PD40_D0.5_S50 413,1450 r270 top value=STD
TP4 "TP-038" TP1_PD40_D0.5_S50 1953,1475 r90 top value=STD
TP5 "TP-038" TP1_PD40_D0.5_S50 1650,1290 r180 top value=STD
TP6 "TP1_PD40_D0.5_S50" TP1_PD40_D0.5_S50 874,951 r0 top value=STD
TP7 "TP1_PD40_D0.5_S50" TP1_PD40_D0.5_S50 2065,996 r0 top value=STD
TP8 "TP1_PD40_D0.5_S50" TP1_PD40_D0.5_S50 1658,860 r0 top value=STD
TP9 "TP-038" TP1_PD40_D0.5_S50 1403,559 r90 top value=STD
TP10 "TP1_PD40_D0.5_S50" TP1_PD40_D0.5_S50 566,360 r0 top value=STD
TP11 "TP1_PD40_D0.5_S50" TP1_PD40_D0.5_S50 1496,189 r90 top value=STD
TP12 "TP1_PD40_D0.5_S50" TP1_PD40_D0.5_S50 774,105 r90 top value=STD
TP13 "TP1_PD40_D0.5_S50" TP1_PD40_D0.5_S50 1490,76 r90 top value=STD
TP14 "5000" Keystone5000 499,2675 r90 top
TP15 "5000" Keystone5000 2232,2319.67 r90 top
TP16 "5001" Keystone5001 499,2375 r90 top
TP17 "5000" Keystone5000 2232,2604.67 r90 top
TP18 "5002" Keystone5002 772,2184 r90 top
TP19 "5004" Keystone5004 929.61,2184 r90 top
TP20 "5000" Keystone5000 2339,2921.88 r90 top
TP21 "5001" Keystone5001 901,2765 r90 top
U1 "TPS7A3001DGNR" MSOP8(DGN) 1825,1833.2 r180 top
U2 "LM5017MRE/NOPB" DDA0008B_N 820,1640 r270 top
U3 "TPS7A4700RGW" RGW0020A 1950,1115 r270 top
U4 "TPS70933DBVT" DBV0005A_N#1 795,640 r270 top
U5 "TPS7A1650DGNR" DGN_8P 1570.6,614.2 r0 top
U6 "ISO7741DBQR" DBQ0016A_N 1110,405 r0 top
U7 "ISO1541D" D0008A_N 1105,150 r0 top
U8 "TPS55010RTER" RTE0016F 1122,2504.67 r0 top
U9 "LP2985-50DBVR" DBV0005A_N#2 2017,2884.67 r0 top
U10 "TVS3300DRVR" DRV0006A 661,1161 r180 top
U11 "TVS0500DRVR" DRV0006A 499,2528 r90 top
ZZ1 "This Assembly Note is for PCB labels only" AssemblyNoteLabel 267,4740 r0 top
ZZ2 "These assemblies are ESD sensitive, ESD precautions shall be observed." AssemblyNote 269,4655.11 r0 top
ZZ3 "These assemblies must be clean and free from flux and all contaminants. Use of no clean flux is not acceptable." AssemblyNote 269,4566.56 r0 top
ZZ4 "These assemblies must comply with workmanship standards IPC-A-610 Class 2, unless otherwise specified." AssemblyNote 269,4478 r0 top

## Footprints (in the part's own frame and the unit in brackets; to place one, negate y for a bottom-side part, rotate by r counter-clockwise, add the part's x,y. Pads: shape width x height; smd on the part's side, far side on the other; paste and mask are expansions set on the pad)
0603 [mm] "0603 from SM-752 data"
  rect 1x0.95 smd: 1(-0.8,0) 2(0.8,0)
  silkscreen extent -1.52,-0.69 1.52,0.69, body extent -0.87,-0.47 0.87,0.47, height 0.85
0805 [mm] "0805 from SM-752 data"
  rect 1.3x1.5 smd: 1(-0.85,0) 2(0.85,0)
  silkscreen extent -1.72,-0.97 1.72,0.97, body extent -1.1,-0.72 1.1,0.72, height 1.1
0805_HV [mil] "0805 with 30mil clearance between pads"
  rect 50x63 smd: 1(-40,0) 2(40,0)
  silkscreen extent -74,-40 74,40, body extent -43,-29 43,29, height 43
1206 [mm] "1206 from SM-752 data"
  rect 1.3x1.85 smd: 1(-1.45,0) 2(1.45,0)
  silkscreen extent -2.4,-1.21 2.4,1.21, body extent -1.7,-0.9 1.7,0.9, height 1.35
1206_180 [mm] "1206_180"
  rect 1.1x1.6 smd: 1(-1.7,0) 2(1.7,0)
  silkscreen extent -0.9,-1 0.9,1, body extent -1.75,-0.95 1.75,0.95, height 1.8
1206_190 [mm] "1206_190"
  rect 1.1x1.6 smd: 1(-1.7,0) 2(1.7,0)
  silkscreen extent -0.9,-1 0.9,1, body extent -1.75,-0.95 1.75,0.95, height 1.9
1210#1 [mm] "1210 from SM-752 data"
  rect 1.3x2.7 smd: 1(-1.45,0) 2(1.45,0)
  silkscreen extent -2.32,-1.57 2.32,1.57, body extent -1.7,-1.35 1.7,1.35, height 1.35
1210#2 [mm]
  rect 1.27x2.794 smd: 1(1.524,0) 2(-1.524,0)
  silkscreen extent -2.54,-1.78 2.54,1.78
1812 [mm]
  rect 1.6x3.4 smd: 1(-2,0) 2(2,0)
  silkscreen extent -0.8,-1.6 0.8,1.6, body extent -2.4,-1.7 2.4,1.7, height 1.35
7343-43 [mm] "Medium density IPC based on Kemet T495 series"
  rect 2.55x2.45 smd: 1(-3.025,0) 2(3.025,0)
  silkscreen extent -4.56,-2.3 3.8,2.3, body extent -3.8,-2.3 3.8,2.3, height 4.3
AssemblyNote [mil] "Assembly Note"
AssemblyNoteLabel [mil] "Assembly Note for PCB Labels"
CAPPRD200W50D500H1100 [mm] "Panasonic"
  rect 1.3x1.3 hole 0.787: 1(-1,0)
  round 1.3 hole 0.787: 2(1,0)
  silkscreen extent -2.75,-2.75 2.75,2.75, body extent -2.73,-2.75 2.75,2.75, height 12.01
CONN_1725711 [mm] "Phoenix Contact"
  rect 1.78x1.78 hole 1.1: 1(-8.89,0)
  round 1.78 hole 1.1: 2(-6.35,0) 3(-3.81,0) 4(-1.27,0) 5(1.27,0) 6(3.81,0) 7(6.35,0) 8(8.89,0)
  silkscreen extent -10.49,-3.6 10.4,3.1, body extent -10.39,-3.1 10.39,3.1, height 8.52
CONN_ED120-2DS [mm] "ONSHORE"
  rect 1.75x1.75 hole 1.25: 1(0,-2.54)
  round 1.75 hole 1.25: 2(0,2.54)
  silkscreen extent -5,-5.6 4,5.12, body extent -5,-5.6 4.15,5.12, height 13.1
D0008A_N [mm] "SOIC, 8-Leads, Body 4.9x3.9mm, Pitch 1.27mm, IPC Medium Density"
  oval 2.2x0.6 smd: 1(-2.4,1.905) 2(-2.4,0.635) 3(-2.4,-0.635) 4(-2.4,-1.905) 5(2.4,-1.905) 6(2.4,-0.635) 7(2.4,0.635) 8(2.4,1.905)
  silkscreen extent -2.92,-2.5 0.9,2.79, body extent -2,-2.5 2,2.5, height 1.75
DBQ0016A_N [mm] "SOP, 16-Leads, Body 4.9x3.9mm, Pitch 0.635mm, IPC Medium Density"
  oval 1.45x0.4 smd: 1(-2.725,2.222) 2(-2.725,1.587) 3(-2.725,0.953) 4(-2.725,0.318) 5(-2.725,-0.318) 6(-2.725,-0.953) 7(-2.725,-1.587) 8(-2.725,-2.222) 9(2.725,-2.222) 10(2.725,-1.587) 11(2.725,-0.953) 12(2.725,-0.318) 13(2.725,0.318) 14(2.725,0.953) 15(2.725,1.587) 16(2.725,2.222)
  silkscreen extent -3.35,-2.5 1.1,2.68, body extent -3.01,-2.45 3.01,2.45, height 1.63
DBV0005A_N#1 [mm] "SOT23, 5-Leads, Body 2.9x1.6mm, Pitch 0.95mm, Lead Span 2.8mm, IPC Medium Density"
  rect 1.1x0.65 smd: 1(-1.2,0.95) 2(-1.2,0) 3(-1.2,-0.95) 4(1.2,-0.95) 5(1.2,0.95)
  silkscreen extent -0.25,-1.55 0.25,1.55, body extent -1.42,-1.46 1.42,1.46, height 1.08
DBV0005A_N#2 [mm] "SOT23, 5-Leads, Body 2.9x1.6mm, Pitch 0.95mm, Lead Span 2.8mm, IPC Medium Density"
  rrect17% 1x0.6 smd: 1(-1.375,0.95) 2(-1.375,0) 3(-1.375,-0.95) 4(1.375,-0.95) 5(1.375,0.95)
  silkscreen extent -1.63,-1.55 0.38,1.55, body extent -1.42,-1.46 1.42,1.46, height 1.09
DDA0008B_N [mm] "SOIC, 8-Leads, Body 4.9x3.9mm, Pitch 1.27mm, Exposed Pad, IPC Medium Density"
  oval 2x0.6 smd: 1(-2.5,1.905) 2(-2.5,0.635) 3(-2.5,-0.635) 4(-2.5,-1.905) 5(2.5,-1.905) 6(2.5,-0.635) 7(2.5,0.635) 8(2.5,1.905)
  rect 2.41x3.1 smd: 9(0,0)
  silkscreen extent -2.62,-2.5 1.1,2.88, body extent -2,-2.5 2,2.5, height 1.68
DGN_8P [mil]
  rect 40x17 smd: 1(-82.1,40) 2(-82.1,14.4) 3(-82.1,-11.2) 4(-82.1,-36.8) 5(82.9,-36.9) 6(82.9,-11.3) 7(82.9,14.3) 8(82.9,40)
  rect 80x80 smd: 9(0.2,1.4)
  silkscreen extent -106,63 -81,88
DIO_SOD-106 [mm] "ZENERDIODE, SOD-106"
  rect 2x2 smd: 1(-2.1,0) 2(2.1,0)
  Top Layer keep-out region: -0.838,-1.3 0.864,-1.3 0.864,1.3 -0.838,1.3
  silkscreen extent -3.5,-1.33 2.25,1.3, body extent -2.25,-1.3 2.25,1.3, height 2.4
DRV0006A [mm] "SON, 6-Leads, Body 2x2mm, Pitch 0.65mm, Thermal Pad 1.6x1mm, TI Recommended"
  rrect33% 0.45x0.3 smd: 1(-0.975,0.65) 2(-0.975,0) 3(-0.975,-0.65) 4(0.975,-0.65) 5(0.975,0) 6(0.975,0.65)
  rrect14% 1x0.7 on Top Paste: 7(0,0.45) 7(0,-0.45)
  rrect10% 1x1.6 smd paste-0.5: 7(0,0)
  silkscreen extent -1.05,-1.2 1.05,1.2, body extent -1.05,-1.05 1.05,1.05, height 0.81
ESD_Overlay_small [mil]
  silkscreen extent -62,-48 64,61
FB0603 [mm]
  rect 0.95x1 smd: 1(-0.75,0) 2(0.75,0)
  silkscreen extent -0.8,-0.7 0.8,0.7
FCC_disclaimer [mil]
FID_TOP_40_80BA [mil]
  round 40 smd mask+20: 1(0,0)
  Top Layer keep-out region: 45,0 41.57,17.22 31.82,31.82 17.22,41.57 0,45 0,45 -17.22,41.57 -31.82,31.82 -41.57,17.22 -45,0 -45,0 -41.57,-17.22 -31.82,-31.82 -17.22,-41.57 0,-45 0,-45 17.22,-41.57 31.82,-31.82 41.57,-17.22 45,0
IND_B82422H [mm]
  rect 1.15x2.7 smd: 1(-1.625,0) 2(1.625,0)
  Top Layer keep-out region: -0.508,-1.135 0.508,-1.135 0.508,1.131 -0.508,1.131
  silkscreen extent -1.6,-1.57 1.6,1.57, body extent -1.6,-1.25 1.6,1.25, height 2.4
Keystone5000 [mil] "For Keystone 500x miniature loop terminals"
  round 80 hole 40: 1(0,0)
  silkscreen extent -52,-52 52,52, body extent -49,-49 49,49, height 182
Keystone5001 [mil] "For Keystone 500x miniature loop terminals"
  round 80 hole 40: 1(0,0)
  silkscreen extent -52,-52 52,52, body extent -49,-49 49,49, height 182
Keystone5002 [mil] "For Keystone 500x miniature loop terminals"
  round 80 hole 40: 1(0,0)
  silkscreen extent -58,-58 58,58, body extent -49,-49 49,49, height 182
Keystone5004 [mil] "For Keystone 500x miniature loop terminals"
  round 80 hole 40: 1(0,0)
  silkscreen extent -58,-58 58,58, body extent -49,-49 49,49, height 182
Label_650x200 [mil] "Thermal Transfer Label"
  silkscreen extent -325,-100 325,100, body extent -325,-100 325,100, height 1
LED0603AA [mil]
  rect 32x32 smd: 1(-32.48,0) 2(32.48,0)
  silkscreen extent -132,-25 11,25
MSOP8(DGN) [mil]
  rect 50x15 smd: 1(-77,38) 2(-77,12.4) 3(-77,-13.2) 4(-77,-38.8) 5(76.6,-38.8) 6(76.6,-13.2) 7(76.6,12.4) 8(76.6,38)
  rect 60x75 smd: 9(0,-0.8)
  silkscreen extent -140,77 -115,102
"NY PMS 440 0025 PH" [mm] "4-40 nylon screw and mounting hole"
  round 8 hole 3.2: 1(0.021,-0.172)
  body extent -3.3,-3.3 3.3,3.3, height 2.69
Pb-Free_Overlay_Small [mil]
powerDI123 [mm] "Diodes Inc recommended land pattern, document number DS30628 Rev. 6-2"
  rect 2.2x1.4 smd: 1(-1.275,0)
  rect 0.9x1.4 smd: 2(1.275,0)
  silkscreen extent -3.1,-1.09 1.76,1.09, body extent -2.38,-0.97 1.52,0.96, height 1
RGW0020A [mm] "QFN, 20-Leads, Body 5x5mm, Pitch 0.65mm, Thermal Pad 3.15x3.15mm, TI Recommended"
  oval 0.75x0.3 smd mask+0.07: 1(-2.325,1.3) 2(-2.325,0.65) 3(-2.325,0) 4(-2.325,-0.65) 5(-2.325,-1.3) 11(2.325,-1.3) 12(2.325,-0.65) 13(2.325,0) 14(2.325,0.65) 15(2.325,1.3)
  oval 0.3x0.75 smd mask+0.07: 6(-1.3,-2.325) 7(-0.65,-2.325) 8(0,-2.325) 9(0.65,-2.325) 10(1.3,-2.325) 16(1.3,2.325) 17(0.65,2.325) 18(0,2.325) 19(-0.65,2.325) 20(-1.3,2.325)
  rect 3.15x3.15 smd paste-1.575 mask+0.07: 21(0,0)
  silkscreen extent -2.73,1.88 -1.88,2.73, body extent -2.58,-2.57 2.57,2.58, height 1.01
RTE0016F [mm] "Texas Insturments"
  rrect42% 0.6x0.24 smd: 1(-1.4,0.75) 2(-1.4,0.25) 3(-1.4,-0.25) 4(-1.4,-0.75) 9(1.4,-0.75) 10(1.4,-0.25) 11(1.4,0.25) 12(1.4,0.75)
  rrect42% 0.24x0.6 smd: 5(-0.75,-1.4) 6(-0.25,-1.4) 7(0.25,-1.4) 8(0.75,-1.4) 13(0.75,1.4) 14(0.25,1.4) 15(-0.25,1.4) 16(-0.75,1.4)
  rrect7% 1.5x1.5 on Top Paste: 17(0,0)
  rrect6% 1.65x1.65 smd paste-0.85: 17(0,0)
  silkscreen extent -1.72,-1.73 1.72,1.73, body extent -1.5,-1.5 1.5,1.5, height 0.8
SOD-123 [mm] "On Semi recommended land pattern"
  rect 0.915x1.22 smd: 1(-1.637,0) 2(1.637,0)
  silkscreen extent -2.75,-1.16 2.03,1.17, body extent -1.93,-0.9 1.93,0.9, height 1.35
SOD-123F [mm] "NXP recommended land pattern"
  rect 1.2x1.2 smd: 1(-1.4,0) 2(1.4,0)
  silkscreen extent -2.64,-1.12 2.01,1.12, body extent -1.8,-0.85 1.8,0.85, height 1.2
SOD-523 [mm] "NXP Semiconductor recommended land pattern, nominal STEP model"
  rect 0.8x0.6 smd: 1(-0.55,0) 2(0.55,0)
  silkscreen extent -1.6,-0.64 1.2,0.63, body extent -0.8,-0.4 0.8,0.4, height 0.72
TE_5-146278-3 [mm] "TE CONNECTIVITY"
  rect 1.65x1.65 hole 1: 1(-2.54,0)
  round 1.65 hole 1: 2(0,0) 3(2.54,0)
  silkscreen extent -4.19,-1.27 3.81,1.27, body extent -3.68,-1.17 3.68,1.17, height 8.13
TEC_282834-4 [mm] "TEC"
  rect 1.6x1.6 hole 1.1: 1(-3.81,0)
  round 1.6 hole 1.1: 2(-1.27,0) 3(1.27,0) 4(3.81,0)
  silkscreen extent -5.44,-3.4 5.44,3.4, body extent -5.31,-3.25 5.31,3.25, height 10.02
TP1_PD40_D0.5_S50 [mil]
  round 40 hole 20: 1(0,0)
  silkscreen extent -25,-25 25,25
WEEE_Minimum [mil] "WEEElie bin"
  silkscreen extent -95,-172 99,104
WURTH_750313995 [mm] "WURTH"
  rect 1.016x1.88 smd: 1(-4.96,8.18) 2(-2.48,8.18) 3(0,8.18) 4(2.48,8.18) 5(4.96,8.18) 6(4.96,-8.18) 7(2.48,-8.18) 8(0,-8.18) 9(-2.48,-8.18) 10(-4.96,-8.18)
  silkscreen extent -6.7,-7.5 6.7,8.5, body extent -6.73,-8.9 6.73,8.9, height 12.7
Wurth_750316170 [mm] "SMT, 8-Leads, Body 9.5x9.78mm, Pitch 2.49mm"
  rect 1.17x1.91 smd: 1(-3.735,4.065) 2(-1.245,4.065) 3(1.245,4.065) 4(3.735,4.065) 5(3.735,-4.065) 6(1.245,-4.065) 7(-1.245,-4.065) 8(-3.735,-4.065)
  silkscreen extent -5.3,-3.5 4.89,3.6, body extent -4.89,-4.75 4.89,4.75, height 10.54
Wurth_60900213421 [mil] "Shunt, 2.54mm, Black"
  round 1 on Mech3: 0(0,0)
  body extent -98,-48 98,48, height 236

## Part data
C1 C21 C22: "CAP, CERM, 2.2uF, 25V, +/-10%, X7R, 0805", Cap_Case=0805, Manufacturer=MuRata, Supplier Part Number 1=490-3331-1-ND, TempCo=X7R, Tolerance_%=10, Value1="0.005 ohm", Value2=25V, ValueDisplayed=2.2µF
C2 C11: "CAP, CERM, 2.2uF, 100V, +/-10%, X7R, 1210", Cap_Case=1210, Manufacturer=MuRata, Supplier Part Number 1=490-3385-1-ND, TempCo=X7R, Tolerance_%=10, Value1="0.007 ohm", Value2=100V, ValueDisplayed=2.2µF
C3: library part GRM31MR72A474KA35L, "CAP, CERM, 0.47uF, 100V, +/-10%, X7R, 1206", Cap_Case=1206, Manufacturer="AVX Corporation", Supplier Part Number 1=478-8032-1-ND, TempCo=X7R, Tolerance_%=10, Value1=Unknown, Value2=100V, ValueDisplayed=0.47µF
C4: library part 1812GC102KA1, "CAP, CERM, 1000pF, 2000V, +/-10%, X7R, 1812", Cap_Case=1812, Manufacturer=AVX, Supplier Part Number 1=478-3000-1-ND, TempCo=X7R, Tolerance_%=10, Value1=Unknown, Value2=2000V, ValueDisplayed=1000pF
C5: "CAP, CERM, 4.7uF, 50V, +/-10%, X7R, 1206", Cap_Case=2220, Manufacturer=MuRata, Supplier Part Number 1=81-GRM31CR71H475KA2L, TempCo=X7R, Tolerance_%=10, Value1=Unknown, Value2=50V, ValueDisplayed=4.7µF
C6 C14 C41: "CAP, CERM, 0.01uF, 100V, +/-5%, X7R, 0603", Cap_Case=0603, Manufacturer=AVX, Supplier Part Number 1=478-3700-1-ND, TempCo=X7R, Tolerance_%=5, Value1="0.098 ohm", Value2=100V, ValueDisplayed=0.01µF
C7 C12 C15 C17 C32 C45: "CAP, CERM, 0.1uF, 50V, +/-10%, X7R, 0603", Cap_Case=0603, Manufacturer=AVX, Supplier Part Number 1=478-5052-1-ND, TempCo=X7R, Tolerance_%=10, Value1=Unknown, Value2=50V, ValueDisplayed=0.1µF
C8: "CAP, CERM, 10uF, 25V, +/-10%, X7R, 1206", Cap_Case=2220, Manufacturer=MuRata, Supplier Part Number 1=81-GRM31CR71E106KA12, TempCo=X7R, Tolerance_%=10, Value1=Unknown, Value2=25V, ValueDisplayed=10µF
C9 C23: "CAP, CERM, 10uF, 50V, +/-10%, X7R, 1210", Cap_Case=1210, Manufacturer=MuRata, Supplier Part Number 1=490-6544-1-ND, TempCo=X7R, Tolerance_%=10, Value1=Unknown, Value2=50V, ValueDisplayed=10µF
C10 C18 C27: "CAP, CERM, 4.7uF, 50V, +/-10%, X5R, 0805", Cap_Case=0805, Manufacturer=TDK, Supplier Part Number 1=445-5980-1-ND, TempCo=X5R, Tolerance_%=10, Value1=Unknown, Value2=50V, ValueDisplayed=4.7µF
C13 C24 C33 C37: library part GRM188R61H105KAALD, "CAP, CERM, 1uF, 50V, +/-10%, X5R, 0603", Cap_Case=0603, Manufacturer="TDK Corporation", Supplier Part Number 1=445-7468-1-ND, TempCo=X5R, Tolerance_%=10, Value1=Unknown, Value2=50V, ValueDisplayed=1µF
C16: "CAP, TA, 47uF, 35V, +/-10%, 0.3 ohm, SMD", Cap_Case=X, Manufacturer=Kemet, Supplier Part Number 1=399-3905-1-ND, Tolerance_%=10, Value1="0.3 ohm", Value2=35V, ValueDisplayed=47µF
C19: "CAP, CERM, 10uF, 35V, +/-20%, X7R, 1210", Cap_Case=1210, Manufacturer="Taiyo Yuden", Supplier Part Number 1=587-2779-1-ND, TempCo=X7R, Tolerance_%=20, Value1=Unknown, Value2=35V, ValueDisplayed=10µF
C20: "CAP, CERM, 1uF, 50V, +/-10%, X7R, 0805", Cap_Case=0805, Manufacturer=AVX, Supplier Part Number 1=478-7956-1-ND, TempCo=X7R, Tolerance_%=10, Value1=Unknown, Value2=50V, ValueDisplayed=1µF
C25 C34 C38 C42: "CAP, CERM, 0.1uF, 100V, +/-10%, X7R, 0603", Cap_Case=0603, Manufacturer=MuRata, Supplier Part Number 1=490-3285-1-ND, TempCo=X7R, Tolerance_%=10, Value1=Unknown, Value2=100V, ValueDisplayed=0.1µF
C26 C30 C35 C36 C39 C40: "CAP, CERM, 0.1uF, 50V, +/-10%, X7R, 0603", Cap_Case=0603, Manufacturer=Kemet, Supplier Part Number 1=399-5089-1-ND, TempCo=X7R, Tolerance_%=10, Value1=Unknown, Value2=50V, ValueDisplayed=0.1µF
C28 C29: "CAP, CERM, 22uF, 16V, +/-20%, X5R, 0805", Cap_Case=0805, Manufacturer=MuRata, TempCo=X5R, Tolerance_%=20, Value1=Unknown, Value2=16V, ValueDisplayed=22µF
C31: "CAP, CERM, 10uF, 16V, +/-20%, X5R, 0805", Cap_Case=0805, Manufacturer=AVX, Supplier Part Number 1=1582704, TempCo=X5R, Tolerance_%=20, Value1=Unknown, Value2=16V, ValueDisplayed=10µF
C43: "CAP, CERM, 3300pF, 100V, +/-5%, X7R, 0603", Cap_Case=0603, Manufacturer=AVX, Supplier Part Number 1=478-3708-1-ND, TempCo=X7R, Tolerance_%=5, Value1="0.159 ohm", Value2=100V, ValueDisplayed=3300pF
C44: "CAP, CERM, 1uF, 25V, +/-10%, X7R, 0603", Cap_Case=0603, Manufacturer=TDK, Supplier Part Number 1=445-5956-1-ND, TempCo=X7R, Tolerance_%=10, Value1=Unknown, Value2=25V, ValueDisplayed=1µF
C46: "CAP, CERM, 1000pF, 100V, +/-5%, X7R, 0603", Cap_Case=0603, Manufacturer=AVX, Supplier Part Number 1=478-3698-1-ND, TempCo=X7R, Tolerance_%=5, Value1="0.276 ohm", Value2=100V, ValueDisplayed=1000pF
C47: "CAP, CERM, 1000 pF, 2000 V, +/- 10%, X7R, 1206_190", Cap_Case=1206, Manufacturer="Johanson Technology", TempCo=X7R, Tolerance_%=10, Value1=Unknown, Value2=2000V, ValueDisplayed=1000pF
C48: "CAP, AL, 47 µF, 35 V, +/- 20%, TH", Cap_Case="RCAP, 5x11mm", Manufacturer=Panasonic, Supplier Part Number 1=P5164-ND, Tolerance_%=20, Value1=Unknown, Value2=35V, ValueDisplayed=47µF
C49 C55 C56: "CAP, CERM, 22 µF, 10 V, +/- 10%, X7R, 1206", Cap_Case=1206, Manufacturer=MuRata, Supplier Part Number 1=490-5309-1-ND, TempCo=X7R, Tolerance_%=10, Value1=Unknown, Value2=10V, ValueDisplayed=22µF
C50 C60 C61: "CAP, CERM, 10 µF, 10 V, +/- 10%, X7R, 0805", Cap_Case=0805, Manufacturer=TDK, Supplier Part Number 1=445-6857-1-ND, TempCo=X7R, Tolerance_%=10, Value1="0.001063 ohm", Value2=10V, ValueDisplayed=10µF
C51 C54: "CAP, CERM, 2.2 µF, 50 V, +/- 10%, X7R, 1206", Cap_Case=1206, Manufacturer=MuRata, Supplier Part Number 1=490-3367-1-ND, TempCo=X7R, Tolerance_%=10, Value1=Unknown, Value2=50V, ValueDisplayed=2.2µF
C52 C59: "CAP, CERM, 0.1 µF, 50 V, +/- 10%, X7R, 0603", Cap_Case=0603, Manufacturer=MuRata, Supplier Part Number 1=490-1519-1-ND, TempCo=X7R, Tolerance_%=10, Value1=Unknown, Value2=50V, ValueDisplayed=0.1µF
C53 C65: "CAP, CERM, 15 pF, 50 V, +/- 5%, C0G/NP0, 0603", Cap_Case=0603, Manufacturer=MuRata, Supplier Part Number 1=490-1407-1-ND, TempCo=C0G/NP0, Tolerance_%=5, Value1=Unknown, Value2=50V, ValueDisplayed=15pF
C57 C58 C63: "CAP, CERM, 2.2 µF, 10 V, +/- 10%, X7R, 0603", Cap_Case=0603, Manufacturer=MuRata, Supplier Part Number 1=490-4520-1-ND, TempCo=X7R, Tolerance_%=10, Value1="0.009 ohm", Value2=10V, ValueDisplayed=2.2µF
C62: "CAP, CERM, 0.033 µF, 50 V, +/- 10%, X7R, 0603", Cap_Case=0603, Manufacturer=MuRata, Supplier Part Number 1=490-3286-1-ND, TempCo=X7R, Tolerance_%=10, Value1=Unknown, Value2=50V, ValueDisplayed=0.033µF
C64: "CAP, CERM, 82 pF, 50 V, +/- 5%, C0G/NP0, 0603", Cap_Case=0603, Manufacturer=MuRata, Supplier Part Number 1=490-1425-1-ND, TempCo=C0G/NP0, Tolerance_%=5, Value1=Unknown, Value2=50V, ValueDisplayed=82pF
C66: "CAP, CERM, 0.01 µF, 100 V, +/- 10%, X7R, 0603", Cap_Case=0603, Manufacturer=AVX, Supplier Part Number 1=478-1205-1-ND, TempCo=X7R, Tolerance_%=10, Value1="0.098 ohm", Value2=100V, ValueDisplayed=0.01µF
